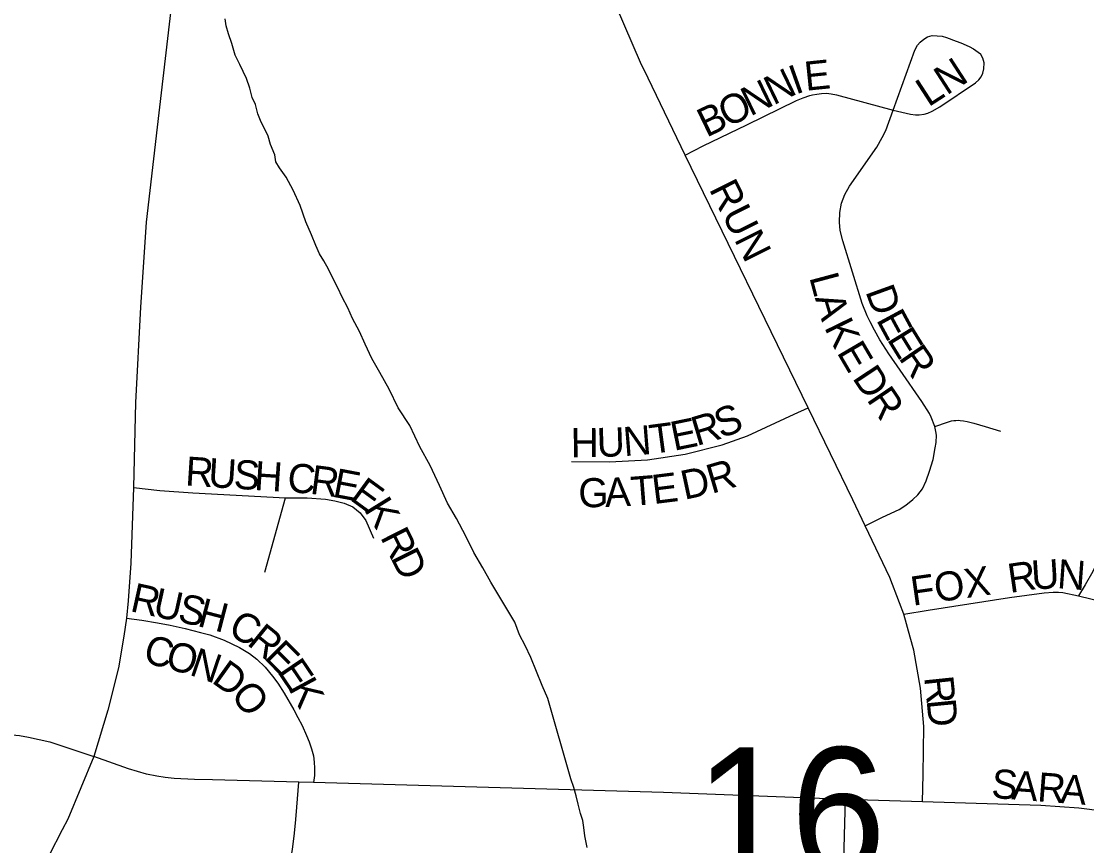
# Model space of a CAD drawing. Extents: x 1587405 to 1714697, y 1028970 to 1155083.
# Drawn here: x 1662922 to 1664754, y 1110570 to 1111987 of the extents above; entities that cross this region are included whole.
import ezdxf

# ---------------------------------------------------------------- set-up
doc = ezdxf.new("R2010")
doc.units = 0
for name, color, linetype in [('GM_X_City_Street', 7, 'Continuous'), ('GM_X_City_Street_Text', 7, 'Continuous'), ('GM_X_Minor_River', 7, 'Continuous'), ('GM_X_Section_Text', 7, 'Continuous')]:
    doc.layers.add(name, color=color, linetype=linetype)

msp = doc.modelspace()

# ---------------------------------------------------------------- linework, layer by layer
at = {"layer": 'GM_X_City_Street'}
for points in [[(1663214.3, 1112280.5), (1663179.9, 1112016.6), (1663155.2, 1111805.4), (1663136.4, 1111642), (1663126.3, 1111496.1), (1663118, 1111332), (1663114.4, 1111185.7)], [(1664063.4, 1111757.4), (1663999.3, 1111889.4), (1663986.1, 1111916.4), (1663945, 1112011.9)], [(1664420.7, 1111834.8), (1664457.9, 1111937.8), (1664462.9, 1111946.2), (1664467, 1111951.3), (1664473.5, 1111956.8), (1664480, 1111960.6), (1664487.7, 1111962.6), (1664496.6, 1111962.5), (1664504.9, 1111961.5), (1664512.6, 1111959.5), (1664529.1, 1111953.4), (1664537, 1111950.4), (1664551.8, 1111943.8), (1664559.2, 1111939.8), (1664570.8, 1111931.2)], [(1664420.7, 1111834.8), (1664450.5, 1111827.5), (1664459.1, 1111826.5), (1664465.7, 1111826.6), (1664474, 1111827.8), (1664480.5, 1111829.5), (1664487.8, 1111832.9), (1664501, 1111840.5), (1664562.2, 1111881.7), (1664568, 1111886.6), (1664572, 1111892.1), (1664575.1, 1111898), (1664576.9, 1111905.4), (1664577.2, 1111915.9), (1664575.3, 1111923.7), (1664570.8, 1111931.2)], [(1664063.4, 1111757.4), (1664093.9, 1111773.1), (1664169.1, 1111809.5), (1664254.6, 1111850.9), (1664265.9, 1111855.7), (1664277.6, 1111859.9), (1664281.9, 1111860.9), (1664289.4, 1111862.3), (1664297.4, 1111863.2), (1664306, 1111863.5), (1664314.4, 1111862.6), (1664323.2, 1111860.9), (1664420.7, 1111834.8)], [(1664492.4, 1111290.7), (1664486.4, 1111307.1), (1664483.1, 1111313.4), (1664470.2, 1111333.8), (1664433.1, 1111387.6), (1664413.3, 1111415.6), (1664398.1, 1111439.7), (1664388.5, 1111456.6), (1664381.2, 1111470.7), (1664376, 1111481.1), (1664367.8, 1111502), (1664334, 1111609.9), (1664329.7, 1111627.8), (1664328.5, 1111642.1), (1664329, 1111658.4), (1664332.2, 1111674.4), (1664337.9, 1111689.7), (1664345.7, 1111704), (1664392.8, 1111770.7), (1664402.2, 1111787.7), (1664408, 1111799.5), (1664420.7, 1111834.8)], [(1664274.5, 1111323), (1664063.4, 1111757.4)], [(1663867.6, 1111230.4), (1663932.8, 1111230.3), (1663998.2, 1111233.5), (1664063.1, 1111243.5), (1664126.7, 1111259.2), (1664170.1, 1111274.7), (1664250.8, 1111312), (1664274.5, 1111323)], [(1664372.8, 1111119.9), (1664351.3, 1111165), (1664274.5, 1111323)], [(1664372.8, 1111119.9), (1664402.6, 1111134.8), (1664430.9, 1111148.3), (1664442.7, 1111155.8), (1664454.8, 1111165.3), (1664463.4, 1111173.3), (1664471, 1111183.5), (1664477.8, 1111197.5), (1664483.6, 1111214), (1664489.4, 1111234), (1664493.2, 1111254), (1664494.5, 1111263), (1664495.1, 1111275.8), (1664494.3, 1111282.1), (1664492.4, 1111290.7)], [(1664492.4, 1111290.7), (1664514.3, 1111298.5), (1664521.2, 1111300.3), (1664524.9, 1111301), (1664528.8, 1111301.3), (1664533.1, 1111301.5), (1664535.9, 1111301.2), (1664541.8, 1111300.4), (1664548, 1111299.3), (1664559.5, 1111296.6), (1664579.1, 1111290.8), (1664605.7, 1111282.8)], [(1663114.4, 1111185.7), (1663109.8, 1111055.8), (1663105.6, 1110991.2), (1663102.4, 1110961.2)], [(1663114.4, 1111185.7), (1663159.7, 1111181), (1663216.5, 1111176.8), (1663376, 1111168.4)], [(1663340.3, 1111040.5), (1663376, 1111168.4)], [(1663376, 1111168.4), (1663413, 1111168), (1663444.6, 1111165.7), (1663460.6, 1111163.2), (1663476.6, 1111159.2), (1663491.7, 1111152.7), (1663504.5, 1111142.6), (1663514, 1111129.1), (1663527.4, 1111099.1)], [(1664794, 1111137.4), (1664776.4, 1111068.1), (1664764.1, 1111041.7), (1664751.2, 1111018.5), (1664739.7, 1110999.6)], [(1664439.1, 1110968.4), (1664431.9, 1110987.6), (1664415.1, 1111031.4), (1664372.8, 1111119.9)], [(1664439.1, 1110968.4), (1664481.3, 1110975), (1664621, 1110997.1), (1664680.4, 1111004.6), (1664695.8, 1111006.1), (1664705, 1111006), (1664712.4, 1111005.4), (1664739.7, 1110999.6), (1664781.9, 1110989.2)], [(1663102.4, 1110961.2), (1663097.6, 1110930.5), (1663088.8, 1110875.9), (1663070.3, 1110803.1), (1663046.3, 1110723.6)], [(1663102.4, 1110961.2), (1663128.7, 1110957.7), (1663155.9, 1110953.5), (1663177.3, 1110949.3), (1663203.5, 1110943.6), (1663229.9, 1110936.9), (1663245.6, 1110932.4), (1663270.2, 1110923.3), (1663296.9, 1110910.8), (1663313.8, 1110900.7), (1663326.8, 1110890.8), (1663340.7, 1110876.9), (1663353.7, 1110861.6), (1663362.6, 1110849.4), (1663373.8, 1110832.5), (1663390.1, 1110803.7), (1663397.3, 1110790.4), (1663404.5, 1110776.6), (1663412.2, 1110759.4), (1663416.7, 1110748.8), (1663420.8, 1110737), (1663423.8, 1110724.8), (1663425.1, 1110713.6), (1663426, 1110703.4), (1663425.7, 1110691), (1663424, 1110678.8)], [(1664471.4, 1110645.5), (1664472.2, 1110692.8), (1664473.5, 1110775.2), (1664467.8, 1110841), (1664456.4, 1110906.1), (1664450.2, 1110928.5), (1664439.1, 1110968.4)], [(1662759.4, 1110759.1), (1662819.1, 1110760.8), (1662849, 1110760.8), (1662898.9, 1110761.2), (1662918.2, 1110759.6), (1662933.7, 1110756.7), (1662970.6, 1110748.5), (1663046.3, 1110723.6)], [(1663046.3, 1110723.6), (1663001.8, 1110615.9), (1662992, 1110597.5), (1662969.6, 1110553.9), (1662936.9, 1110497.5), (1662901.3, 1110442.7), (1662872.7, 1110403), (1662831.9, 1110351.9), (1662788.3, 1110303.4), (1662753.7, 1110268.7), (1662717.5, 1110235.9), (1662654, 1110184.5), (1662511.3, 1110075.5)], [(1663398.7, 1110679.6), (1663250.5, 1110683.2), (1663219.4, 1110684), (1663184.6, 1110686), (1663168.7, 1110687.6), (1663154.4, 1110689.7), (1663137.1, 1110693.4), (1663106, 1110702.6), (1663046.3, 1110723.6)], [(1663310.1, 1110355.4), (1663349.4, 1110432.9), (1663362.2, 1110462.3), (1663372.5, 1110493.3), (1663384.2, 1110541.2), (1663388.5, 1110568.2), (1663391.4, 1110592), (1663393.9, 1110615.3), (1663395.5, 1110636.2), (1663398.7, 1110679.6)], [(1663424, 1110678.8), (1663398.7, 1110679.6)], [(1664338.9, 1110649.5), (1664025.7, 1110661.4), (1663424, 1110678.8)], [(1664328.6, 1110263.7), (1664337.8, 1110608.9), (1664338.9, 1110649.5)], [(1664471.4, 1110645.5), (1664338.9, 1110649.5)], [(1665279.8, 1110579.8), (1665177.2, 1110582.2), (1665062.9, 1110590), (1664981.9, 1110599.6), (1664821.6, 1110624.5), (1664740.2, 1110634.5), (1664674.6, 1110639.3), (1664471.4, 1110645.5)]]:
    msp.add_lwpolyline(points, dxfattribs=at)
at = {"layer": 'GM_X_Minor_River'}
for points in [[(1663866.8, 1110685.1), (1663827.2, 1110823.3), (1663817.4, 1110845.5), (1663807.7, 1110869.7), (1663797.9, 1110894), (1663788.1, 1110914.2), (1663778.2, 1110932.4), (1663770.5, 1110954.6), (1663729, 1111023.4), (1663715.3, 1111047.7), (1663699.5, 1111074.1), (1663685.7, 1111102.4), (1663670, 1111132.7), (1663654.2, 1111159), (1663640.5, 1111189.3), (1663624.8, 1111223.7), (1663607.1, 1111256.1), (1663589.4, 1111292.5), (1663569.7, 1111322.9), (1663554, 1111355.2), (1663538.2, 1111383.5), (1663524.4, 1111407.8), (1663512.7, 1111432.1), (1663502.9, 1111454.3), (1663491.1, 1111476.6), (1663483.2, 1111494.8), (1663473.4, 1111513), (1663465.6, 1111529.1), (1663459.7, 1111541.3), (1663449.8, 1111561.5), (1663442, 1111575.6), (1663434.1, 1111587.8), (1663428.2, 1111601.9), (1663420.4, 1111620.1), (1663410.6, 1111642.3), (1663400.9, 1111670.6), (1663389.1, 1111696.9), (1663377.3, 1111719.1), (1663365.4, 1111735.3), (1663359.5, 1111745.5), (1663357.7, 1111757.6), (1663349.8, 1111775.7), (1663346, 1111789.8), (1663340.1, 1111802), (1663334.2, 1111814.1), (1663328.4, 1111828.2), (1663324.5, 1111844.4), (1663318.6, 1111856.5), (1663314.8, 1111872.6), (1663309, 1111888.8), (1663297.2, 1111913), (1663289.4, 1111929.2), (1663283.6, 1111949.4), (1663277.7, 1111965.5), (1663273.9, 1111979.6), (1663272, 1111991.7)], [(1663888.9, 1110601.5), (1663887, 1110613.6), (1663883.1, 1110625.7), (1663879.3, 1110641.8), (1663875.5, 1110655.9), (1663871.6, 1110670), (1663866.8, 1110685.1)], [(1663894.5, 1110567.3), (1663890.7, 1110587.4), (1663888.9, 1110601.5)]]:
    msp.add_lwpolyline(points, dxfattribs=at)

# ---------------------------------------------------------------- texts
at = {"layer": 'GM_X_City_Street_Text'}
for s, rotation, p in [('I', 19.5685, (1664253, 1111861)), ('E', 5.8846, (1664270.6, 1111867.7)), ('LN', 32.909, (1664481.4, 1111839)), ('N', 25.8026, (1664214.7, 1111842.4)), ('N', 25.8026, (1664175.1, 1111823.3)), ('O', 25.8026, (1664135.5, 1111804.1)), ('B', 25.8048, (1664099.8, 1111786.9)), ('RUN', 296.5583, (1664103.6, 1111699.1)), ('L', 285.0036, (1664276.3, 1111547.5)), ('D', 289.8935, (1664372.7, 1111523.1)), ('A', 286.6541, (1664285.9, 1111512)), ('E', 298.4394, (1664390.9, 1111474.4)), ('K', 296.0161, (1664301.7, 1111461.5)), ('E', 301.6439, (1664409.2, 1111440.9)), ('E', 300.4116, (1664323, 1111418.3)), ('R', 304.384, (1664429.1, 1111408.8)), ('D', 303.5707, (1664349.6, 1111374.3)), ('R', 304.1345, (1664374.2, 1111337.2)), ('S', 20.9237, (1664124.8, 1111269.7)), ('E', 11.5313, (1664043.8, 1111248.8)), ('R', 16.5966, (1664082.9, 1111257)), ('H', 0.3279, (1663866.4, 1111237.9)), ('U', 1.864, (1663911.9, 1111238.2)), ('N', 4.543, (1663958.4, 1111239.7)), ('T', 7.5988, (1664005.2, 1111243.5)), ('R', 356.3055, (1663202.5, 1111189.5)), ('U', 356.3037, (1663242, 1111186.9)), ('S', 356.3095, (1663285.9, 1111184.1)), ('H', 356.3037, (1663321.1, 1111181.8)), ('R', 16.3488, (1664108.7, 1111174.8)), ('C', 355.8434, (1663378, 1111178.2)), ('R', 352.4744, (1663416.8, 1111175.4)), ('E', 349.2528, (1663455.3, 1111170.3)), ('E', 7.1357, (1664009.1, 1111157.3)), ('D', 12.1637, (1664061.8, 1111164.6)), ('E', 323.8842, (1663484.5, 1111166.1)), ('G', 0.3498, (1663879.6, 1111151.9)), ('A', 2.6308, (1663925.8, 1111152.2)), ('T', 4.5439, (1663971.6, 1111154.3)), ('K', 301.7436, (1663509.5, 1111149)), ('R', 296.6411, (1663538, 1111100.9)), ('D', 296.5553, (1663555.8, 1111065.5)), ('FOX', 8.1334, (1664454.6, 1110982.6)), ('R', 8.2846, (1664621.6, 1111004.6)), ('U', 3.6963, (1664659.8, 1111010.2)), ('N', 355.7555, (1664701.8, 1111013)), ('R', 347.5423, (1663107, 1110973.7)), ('U', 347.5328, (1663145.7, 1110965.2)), ('S', 347.5275, (1663188.7, 1110955.7)), ('H', 345.3966, (1663222.6, 1110948.2)), ('C', 333.4893, (1663274.8, 1110933)), ('R', 320.8661, (1663307.8, 1110916.9)), ('C', 344.7385, (1663129, 1110886.2)), ('O', 344.6011, (1663167.2, 1110875.8)), ('E', 314.7682, (1663337.4, 1110892.8)), ('N', 341.1226, (1663208.8, 1110864.3)), ('D', 324.5335, (1663247, 1110851.8)), ('E', 304.1145, (1663360.7, 1110869.7)), ('O', 307.9191, (1663280.1, 1110828.9)), ('K', 298.4814, (1663379.7, 1110841.7)), ('R', 275.9353, (1664474.1, 1110859.9)), ('D', 275.6693, (1664478.2, 1110820.5)), ('S', 355.6788, (1664588.7, 1110652.6)), ('A', 355.6683, (1664623.7, 1110650)), ('R', 355.6637, (1664667.6, 1110646.7)), ('A', 355.6683, (1664707.1, 1110643.7))]:
    msp.add_text(s, height=50, rotation=rotation, dxfattribs=at).set_placement(p)
at = {"layer": 'GM_X_Section_Text'}
msp.add_text('16', height=221, rotation=0, dxfattribs=at).set_placement((1664079.8, 1110518.2))

doc.saveas('drawing.dxf')
